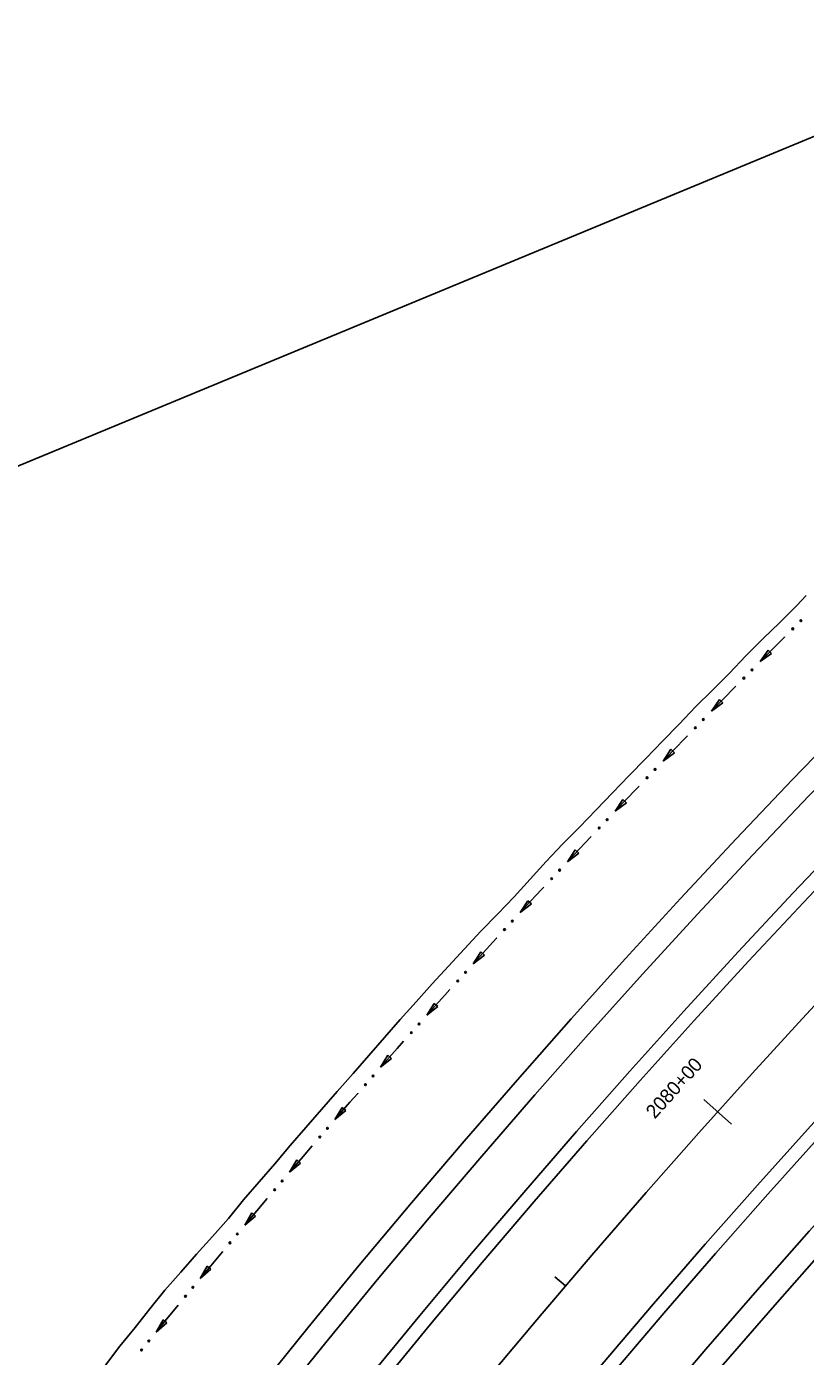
# Model space of a CAD drawing. Extents: x 1611108 to 1749517, y 619561 to 797725.
# Drawn here: x 1714286 to 1714623, y 764673 to 765248 of the extents above; entities that cross this region are included whole.
import ezdxf

# ---------------------------------------------------------------- set-up
doc = ezdxf.new("R2010")
doc.units = 0
for name, color, linetype in [('R_Ditch', 7, 'Continuous'), ('R_Horz Alg', 7, 'Continuous'), ('R_Horz Alg Annot', 7, 'Continuous'), ('R_Horz Alg Stationing', 7, 'Continuous'), ('R_Proposed Const Limits', 7, 'Continuous'), ('R_Proposed Road', 7, 'Continuous')]:
    doc.layers.add(name, color=color, linetype=linetype)

msp = doc.modelspace()

# ---------------------------------------------------------------- linework, layer by layer
at = {"layer": 'R_Ditch'}
for p, q in [((1714606.89, 764978.53), (1714603.43, 764973.52)), ((1714606.89, 764978.53), (1714603.43, 764973.52)), ((1714603.43, 764973.52), (1714608.4, 764977.04)), ((1714603.43, 764973.52), (1714608.4, 764977.04)), ((1714608.4, 764977.04), (1714606.89, 764978.53)), ((1714608.4, 764977.04), (1714606.89, 764978.53)), ((1714585.81, 764957.13), (1714582.37, 764952.1)), ((1714585.81, 764957.13), (1714582.37, 764952.1)), ((1714582.37, 764952.1), (1714587.32, 764955.65)), ((1714582.37, 764952.1), (1714587.32, 764955.65)), ((1714587.32, 764955.65), (1714585.81, 764957.13)), ((1714587.32, 764955.65), (1714585.81, 764957.13)), ((1714564.87, 764935.59), (1714561.46, 764930.53)), ((1714564.87, 764935.59), (1714561.46, 764930.53)), ((1714566.39, 764934.12), (1714564.87, 764935.59)), ((1714566.39, 764934.12), (1714564.87, 764935.59)), ((1714561.46, 764930.53), (1714566.39, 764934.12)), ((1714561.46, 764930.53), (1714566.39, 764934.12)), ((1714544.07, 764913.91), (1714540.7, 764908.83)), ((1714544.07, 764913.91), (1714540.7, 764908.83)), ((1714540.7, 764908.83), (1714545.6, 764912.45)), ((1714540.7, 764908.83), (1714545.6, 764912.45)), ((1714545.6, 764912.45), (1714544.07, 764913.91)), ((1714545.6, 764912.45), (1714544.07, 764913.91)), ((1714523.41, 764892.09), (1714520.08, 764886.99)), ((1714523.41, 764892.09), (1714520.08, 764886.99)), ((1714520.08, 764886.99), (1714524.95, 764890.64)), ((1714520.08, 764886.99), (1714524.95, 764890.64)), ((1714524.95, 764890.64), (1714523.41, 764892.09)), ((1714524.95, 764890.64), (1714523.41, 764892.09)), ((1714502.91, 764870.12), (1714499.62, 764864.99)), ((1714502.91, 764870.12), (1714499.62, 764864.99)), ((1714499.62, 764864.99), (1714504.47, 764868.68)), ((1714499.62, 764864.99), (1714504.47, 764868.68)), ((1714504.47, 764868.68), (1714502.91, 764870.12)), ((1714504.47, 764868.68), (1714502.91, 764870.12)), ((1714482.59, 764847.99), (1714479.33, 764842.84)), ((1714482.59, 764847.99), (1714479.33, 764842.84)), ((1714484.16, 764846.56), (1714482.59, 764847.99)), ((1714484.16, 764846.56), (1714482.59, 764847.99)), ((1714479.33, 764842.84), (1714484.16, 764846.56)), ((1714479.33, 764842.84), (1714484.16, 764846.56)), ((1714462.44, 764825.71), (1714459.21, 764820.54)), ((1714462.44, 764825.71), (1714459.21, 764820.54)), ((1714464.01, 764824.29), (1714462.44, 764825.71)), ((1714464.01, 764824.29), (1714462.44, 764825.71)), ((1714459.21, 764820.54), (1714464.01, 764824.29)), ((1714459.21, 764820.54), (1714464.01, 764824.29)), ((1714442.45, 764803.27), (1714439.27, 764798.08)), ((1714442.45, 764803.27), (1714439.27, 764798.08)), ((1714444.03, 764801.87), (1714442.45, 764803.27)), ((1714444.03, 764801.87), (1714442.45, 764803.27)), ((1714439.27, 764798.08), (1714444.03, 764801.87)), ((1714439.27, 764798.08), (1714444.03, 764801.87)), ((1714422.63, 764780.69), (1714419.49, 764775.47)), ((1714422.63, 764780.69), (1714419.49, 764775.47)), ((1714419.49, 764775.47), (1714424.23, 764779.3)), ((1714419.49, 764775.47), (1714424.23, 764779.3)), ((1714424.23, 764779.3), (1714422.63, 764780.69)), ((1714424.23, 764779.3), (1714422.63, 764780.69)), ((1714402.99, 764757.95), (1714399.89, 764752.71)), ((1714402.99, 764757.95), (1714399.89, 764752.71)), ((1714399.89, 764752.71), (1714404.6, 764756.57)), ((1714399.89, 764752.71), (1714404.6, 764756.57)), ((1714404.6, 764756.57), (1714402.99, 764757.95)), ((1714404.6, 764756.57), (1714402.99, 764757.95)), ((1714383.52, 764735.07), (1714380.46, 764729.8)), ((1714383.52, 764735.07), (1714380.46, 764729.8)), ((1714380.46, 764729.8), (1714385.14, 764733.7)), ((1714380.46, 764729.8), (1714385.14, 764733.7)), ((1714385.14, 764733.7), (1714383.52, 764735.07)), ((1714385.14, 764733.7), (1714383.52, 764735.07)), ((1714364.22, 764712.03), (1714361.21, 764706.74)), ((1714364.22, 764712.03), (1714361.21, 764706.74)), ((1714361.21, 764706.74), (1714365.85, 764710.68)), ((1714361.21, 764706.74), (1714365.85, 764710.68)), ((1714365.85, 764710.68), (1714364.22, 764712.03)), ((1714365.85, 764710.68), (1714364.22, 764712.03)), ((1714345.11, 764688.86), (1714342.13, 764683.54)), ((1714345.11, 764688.86), (1714342.13, 764683.54)), ((1714342.13, 764683.54), (1714346.74, 764687.52)), ((1714342.13, 764683.54), (1714346.74, 764687.52)), ((1714346.74, 764687.52), (1714345.11, 764688.86)), ((1714346.74, 764687.52), (1714345.11, 764688.86))]:
    msp.add_line(p, q, dxfattribs=at)
for points in [[(1714613.99, 764984.17), (1714608.93, 764979.09), (1714603.43, 764973.52)], [(1714613.99, 764984.17), (1714608.93, 764979.09), (1714603.43, 764973.52)], [(1714614.02, 764984.2), (1714613.99, 764984.17)], [(1714614.02, 764984.2), (1714613.99, 764984.17)], [(1714592.87, 764962.81), (1714587.21, 764957.05), (1714582.37, 764952.1)], [(1714592.87, 764962.81), (1714587.21, 764957.05), (1714582.37, 764952.1)], [(1714592.89, 764962.84), (1714592.87, 764962.82)], [(1714592.89, 764962.84), (1714592.87, 764962.82)], [(1714571.89, 764941.32), (1714565.64, 764934.86), (1714561.46, 764930.53)], [(1714571.89, 764941.32), (1714565.64, 764934.86), (1714561.46, 764930.53)], [(1714571.91, 764941.35), (1714571.89, 764941.32)], [(1714571.91, 764941.35), (1714571.89, 764941.32)], [(1714551.05, 764919.68), (1714544.22, 764912.53), (1714540.7, 764908.83)], [(1714551.05, 764919.68), (1714544.22, 764912.53), (1714540.7, 764908.83)], [(1714551.08, 764919.71), (1714551.05, 764919.69)], [(1714551.08, 764919.71), (1714551.05, 764919.69)], [(1714530.35, 764897.91), (1714530.02, 764897.56), (1714522.95, 764890.05), (1714520.08, 764886.99)], [(1714530.35, 764897.91), (1714530.02, 764897.56), (1714522.95, 764890.05), (1714520.08, 764886.99)], [(1714530.38, 764897.94), (1714530.35, 764897.91)], [(1714530.38, 764897.94), (1714530.35, 764897.91)], [(1714509.82, 764875.99), (1714508.86, 764874.97), (1714501.85, 764867.4), (1714499.62, 764864.99)], [(1714509.82, 764875.99), (1714508.86, 764874.97), (1714501.85, 764867.4), (1714499.62, 764864.99)], [(1714509.84, 764876.02), (1714509.82, 764875.99)], [(1714509.84, 764876.02), (1714509.82, 764875.99)], [(1714489.44, 764853.92), (1714487.88, 764852.21), (1714480.92, 764844.59), (1714479.33, 764842.84)], [(1714489.44, 764853.92), (1714487.88, 764852.21), (1714480.92, 764844.59), (1714479.33, 764842.84)], [(1714489.47, 764853.95), (1714489.44, 764853.92)], [(1714489.47, 764853.95), (1714489.44, 764853.92)], [(1714469.24, 764831.69), (1714467.07, 764829.29), (1714460.18, 764821.61), (1714459.22, 764820.53)], [(1714469.24, 764831.69), (1714467.07, 764829.29), (1714460.18, 764821.61), (1714459.22, 764820.53)], [(1714469.27, 764831.72), (1714469.24, 764831.69)], [(1714469.27, 764831.72), (1714469.24, 764831.69)], [(1714449.21, 764809.31), (1714446.45, 764806.2), (1714439.61, 764798.47), (1714439.27, 764798.08)], [(1714449.21, 764809.31), (1714446.45, 764806.2), (1714439.61, 764798.47), (1714439.27, 764798.08)], [(1714449.23, 764809.34), (1714449.21, 764809.31)], [(1714449.23, 764809.34), (1714449.21, 764809.31)], [(1714429.35, 764786.77), (1714426, 764782.95), (1714419.49, 764775.47)], [(1714429.35, 764786.77), (1714426, 764782.95), (1714419.49, 764775.47)], [(1714429.37, 764786.8), (1714429.35, 764786.77)], [(1714429.37, 764786.8), (1714429.35, 764786.77)], [(1714409.66, 764764.09), (1714405.74, 764759.53), (1714399.89, 764752.71)], [(1714409.66, 764764.09), (1714405.74, 764759.53), (1714399.89, 764752.71)], [(1714409.68, 764764.12), (1714409.66, 764764.09)], [(1714409.68, 764764.12), (1714409.66, 764764.09)], [(1714390.14, 764741.25), (1714385.66, 764735.96), (1714380.46, 764729.8)], [(1714390.14, 764741.25), (1714385.66, 764735.96), (1714380.46, 764729.8)], [(1714390.17, 764741.28), (1714390.14, 764741.25)], [(1714390.17, 764741.28), (1714390.14, 764741.25)], [(1714370.8, 764718.27), (1714365.76, 764712.23), (1714361.21, 764706.74)], [(1714370.8, 764718.27), (1714365.76, 764712.23), (1714361.21, 764706.74)], [(1714370.82, 764718.3), (1714370.8, 764718.27)], [(1714370.82, 764718.3), (1714370.8, 764718.27)], [(1714351.63, 764695.14), (1714346.04, 764688.33), (1714342.13, 764683.54)], [(1714351.63, 764695.14), (1714346.04, 764688.33), (1714342.13, 764683.54)], [(1714351.66, 764695.17), (1714351.63, 764695.14)], [(1714351.66, 764695.17), (1714351.63, 764695.14)]]:
    msp.add_lwpolyline(points, dxfattribs=at)
for centre in [(1714617.56, 764987.7), (1714617.56, 764987.7), (1714621.1, 764991.25), (1714621.1, 764991.25), (1714599.93, 764969.94), (1714599.93, 764969.94), (1714596.42, 764966.37), (1714596.42, 764966.37), (1714578.9, 764948.49), (1714578.9, 764948.49), (1714575.41, 764944.9), (1714575.41, 764944.9), (1714554.55, 764923.28), (1714554.55, 764923.28), (1714558.02, 764926.9), (1714558.02, 764926.9), (1714537.28, 764905.17), (1714537.28, 764905.17), (1714533.83, 764901.54), (1714533.83, 764901.54), (1714516.68, 764883.31), (1714516.68, 764883.31), (1714513.27, 764879.64), (1714513.27, 764879.64), (1714496.26, 764861.28), (1714496.26, 764861.28), (1714492.87, 764857.6), (1714492.87, 764857.6), (1714476, 764839.11), (1714476, 764839.11), (1714472.63, 764835.39), (1714472.63, 764835.39), (1714455.91, 764816.78), (1714455.91, 764816.78), (1714452.57, 764813.04), (1714452.57, 764813.04), (1714432.68, 764790.53), (1714432.68, 764790.53), (1714435.99, 764794.29), (1714435.99, 764794.29), (1714412.96, 764767.87), (1714412.96, 764767.87), (1714416.24, 764771.66), (1714416.24, 764771.66), (1714393.42, 764745.06), (1714393.42, 764745.06), (1714396.67, 764748.87), (1714396.67, 764748.87), (1714374.05, 764722.1), (1714374.05, 764722.1), (1714377.27, 764725.94), (1714377.27, 764725.94), (1714354.85, 764699), (1714354.85, 764699), (1714358.04, 764702.86), (1714358.04, 764702.86), (1714335.84, 764675.75), (1714335.84, 764675.75), (1714338.99, 764679.64), (1714338.99, 764679.64)]:
    msp.add_circle(centre, 0.375, dxfattribs=at)
at = {"layer": 'R_Horz Alg'}
msp.add_arc((1717426.61, 762226.09), 3819.72, 112.5, 179.5, dxfattribs=at)
at = {"layer": 'R_Horz Alg Annot'}
msp.add_line((1713629.09, 764787.55), (1715964.86, 765755.05), dxfattribs=at)
at = {"layer": 'R_Horz Alg Stationing'}
for points in [[(1714579.14, 764784.1), (1714591.04, 764773.4)], [(1714514.68, 764707.39), (1714519.25, 764703.49)]]:
    msp.add_lwpolyline(points, dxfattribs=at)
at = {"layer": 'R_Proposed Const Limits'}
msp.add_lwpolyline([(1714320.24, 764669.23), (1714326.5, 764677.47), (1714333, 764685.52), (1714339.46, 764693.6), (1714345.91, 764701.69), (1714352.76, 764709.46), (1714359.66, 764717.18), (1714366.57, 764724.89), (1714373.41, 764732.66), (1714379.94, 764740.68), (1714386.73, 764748.48), (1714393.47, 764756.33), (1714400.18, 764764.19), (1714406.92, 764772.04), (1714413.69, 764779.86), (1714420.51, 764787.63), (1714427.35, 764795.38), (1714434.16, 764803.16), (1714440.96, 764810.95), (1714447.78, 764818.72), (1714454.69, 764826.41), (1714461.62, 764834.08), (1714468.58, 764841.73), (1714475.57, 764849.35), (1714482.58, 764856.94), (1714489.82, 764864.34), (1714497.05, 764871.73), (1714504.01, 764879.38), (1714510.86, 764887.11), (1714518.01, 764894.58), (1714525.28, 764901.93), (1714532.45, 764909.37), (1714539.65, 764916.79), (1714546.85, 764924.2), (1714554.04, 764931.62), (1714561.22, 764939.05), (1714568.45, 764946.43), (1714575.51, 764953.97), (1714582.86, 764961.23), (1714590.14, 764968.57), (1714597.34, 764975.97), (1714604.61, 764983.31), (1714612.04, 764990.49), (1714619.35, 764997.78), (1714623.34, 765002.1)], dxfattribs=at)
at = {"layer": 'R_Proposed Road'}
for radius in [3893.72, 3883.72, 3859.72, 3853.72, 3785.72, 3779.72, 3755.72, 3745.72]:
    msp.add_arc((1717426.61, 762226.09), radius, 112.5, 179.5, dxfattribs=at)

# ---------------------------------------------------------------- texts
at = {"layer": 'R_Horz Alg Stationing'}
msp.add_text('2080+00', height=6, rotation=48.06525, dxfattribs=at).set_placement((1714557.9, 764775.42))

doc.saveas('drawing.dxf')
